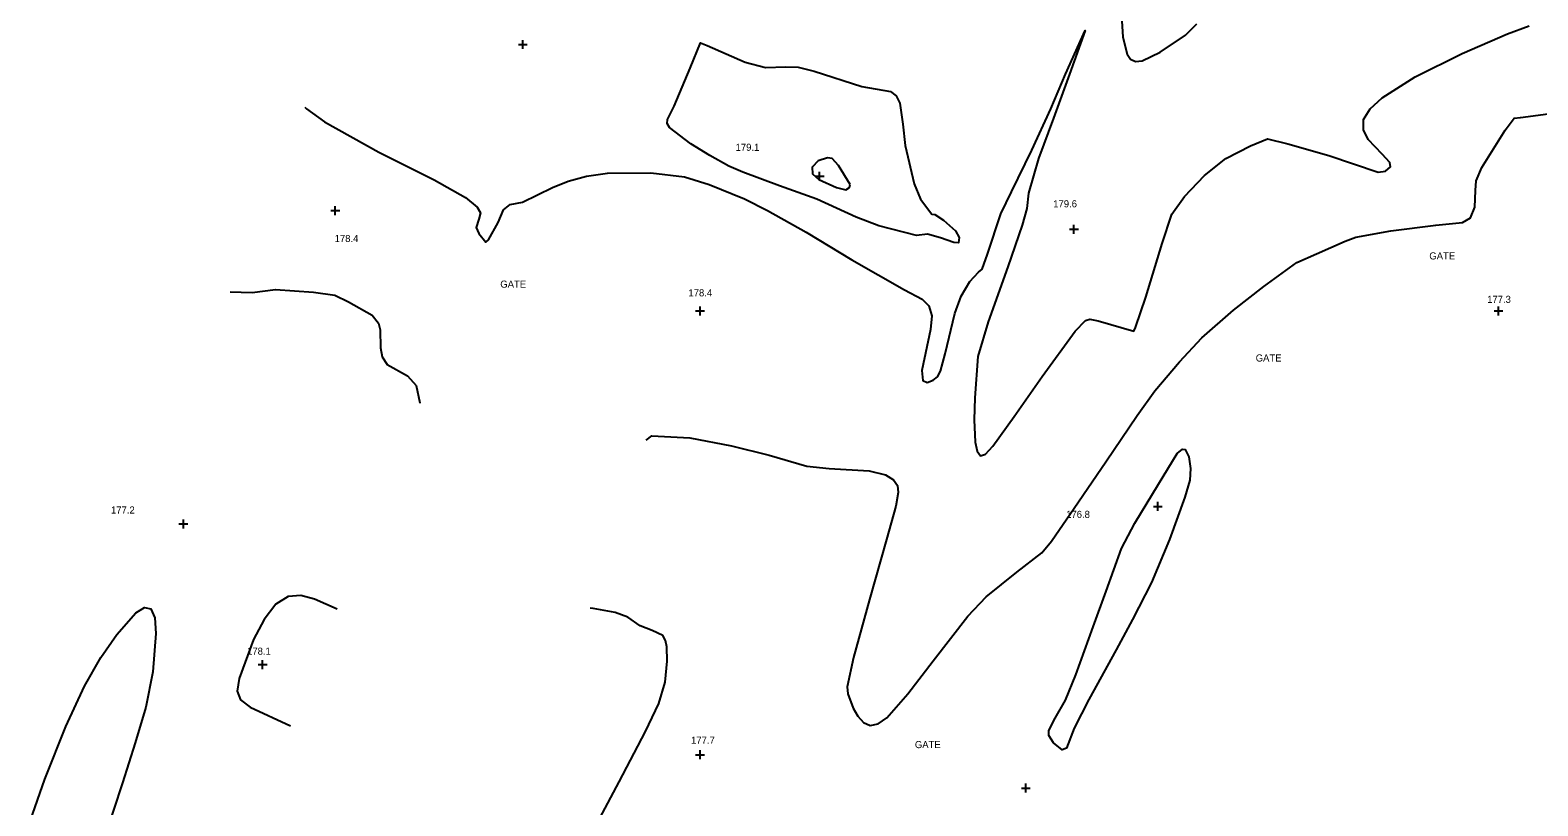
# Model space of a CAD drawing. Extents: x 1475150 to 2003689, y 770235 to 1112803.
# Drawn here: x 1997136.2 to 1997561.1, y 776485.6 to 776704.1 of the extents above; entities that cross this region are included whole.
import ezdxf

# ---------------------------------------------------------------- set-up
doc = ezdxf.new("R2010")
doc.units = 0
for name, color, linetype in [('RD_DTM_Major1', 7, 'Continuous'), ('RD_DTM_Minor1', 7, 'Continuous'), ('RD_DTM_Spot_Elev', 7, 'Continuous'), ('RD_TX_Misc1', 7, 'Continuous')]:
    doc.layers.add(name, color=color, linetype=linetype)

msp = doc.modelspace()

# ---------------------------------------------------------------- linework, layer by layer
at = {"layer": 'RD_DTM_Major1'}
msp.add_lwpolyline([(1997443.54, 776711.31), (1997444.13, 776702.06), (1997445.33, 776697.3), (1997446.33, 776695.91), (1997447.72, 776695.28), (1997449.6, 776695.44), (1997454.69, 776697.86), (1997461.79, 776702.67), (1997465.01, 776705.84)], dxfattribs=at)
at = {"layer": 'RD_DTM_Minor1'}
for points in [[(1997213.6, 776682.39), (1997214.08, 776681.94), (1997219.15, 776678.26), (1997234.51, 776669.73), (1997250.05, 776661.89), (1997258.86, 776656.95), (1997262.23, 776654.26), (1997263.12, 776652.61), (1997262.63, 776650.87), (1997261.92, 776648.45), (1997262.65, 776646.82), (1997264.63, 776644.36), (1997265.4, 776645.05), (1997268.13, 776649.88), (1997269.63, 776653.46), (1997271.47, 776654.94), (1997275, 776655.63), (1997283.44, 776659.79), (1997287.81, 776661.55), (1997292.99, 776662.96), (1997298.9, 776663.77), (1997311.13, 776663.87), (1997320.62, 776662.72), (1997327.54, 776660.62), (1997337.51, 776656.52), (1997343.96, 776653.32), (1997354.85, 776647.14), (1997367.79, 776639.37), (1997382.58, 776630.9), (1997387.56, 776628.27), (1997389.47, 776626.39), (1997390.35, 776623.62), (1997389.91, 776619.75), (1997387.46, 776608.22), (1997387.79, 776605.41), (1997388.97, 776604.81), (1997390.65, 776605.45), (1997391.89, 776606.4), (1997392.72, 776608.04), (1997394.09, 776612.89), (1997396.76, 776624.3), (1997398.55, 776629.13), (1997401.01, 776633.29), (1997403.5, 776635.89), (1997404.45, 776636.8), (1997405.98, 776640.96), (1997409.71, 776652.3), (1997412.76, 776658.55), (1997418.49, 776670.25), (1997423.8, 776681.93), (1997427.96, 776691.69), (1997433.55, 776703.99), (1997429.12, 776691.68), (1997424.61, 776679.28), (1997420.39, 776667.91), (1997417.54, 776658.15), (1997417.09, 776653.88), (1997415.81, 776649.15), (1997411.7, 776637.38), (1997406.17, 776621.88), (1997403.31, 776612.2), (1997402.44, 776600.51), (1997402.27, 776594.29), (1997402.53, 776588.03), (1997403.05, 776585.45), (1997403.99, 776584.15), (1997405.47, 776584.67), (1997407.54, 776586.87), (1997413.5, 776595.23), (1997421.44, 776606.5), (1997430.74, 776619.25), (1997433.6, 776622.33), (1997434.82, 776622.64), (1997437.15, 776622.18), (1997447.21, 776619.34), (1997447.69, 776620.3), (1997450.6, 776628.88), (1997455.2, 776643.95), (1997457.94, 776652.28), (1997461.49, 776657.25), (1997467.17, 776663.15), (1997473.19, 776667.89), (1997480.09, 776671.52), (1997484.88, 776673.44), (1997490.65, 776672.08), (1997502.21, 776668.77), (1997516.08, 776664.12), (1997518.15, 776664.36), (1997519.59, 776665.56), (1997519.38, 776666.76), (1997517.23, 776669.12), (1997513.25, 776673.32), (1997511.91, 776675.98), (1997511.93, 776678.9), (1997513.81, 776681.95), (1997517.22, 776685.05), (1997526.47, 776690.88), (1997539.73, 776697.45), (1997552.56, 776703.07), (1997558.68, 776705.31)], [(1997317.74, 776682.62), (1997322.21, 776693.35), (1997325.16, 776700.47), (1997327, 776699.72), (1997337.66, 776695.09), (1997343.39, 776693.59), (1997349.21, 776693.7), (1997352.65, 776693.62), (1997357.19, 776692.53), (1997370.58, 776688.2), (1997378.66, 776686.78), (1997380.29, 776685.57), (1997381.29, 776683.48), (1997382.1, 776677.6), (1997382.76, 776671.54), (1997385.32, 776660.76), (1997387.08, 776656.44), (1997390.28, 776652.22), (1997391.16, 776652.16), (1997393.58, 776650.59), (1997397.02, 776647.57), (1997398.05, 776645.71), (1997397.81, 776644.21), (1997396.52, 776644.29), (1997392.78, 776645.55), (1997389.1, 776646.6), (1997386, 776646.19), (1997375.36, 776648.96), (1997369, 776651.37), (1997357.91, 776656.44), (1997347.36, 776660.25), (1997337.03, 776664.08), (1997333.06, 776665.75), (1997327.74, 776668.8), (1997322.37, 776672.05), (1997316.36, 776676.65), (1997315.7, 776677.77), (1997315.82, 776678.88), (1997317.74, 776682.62)], [(1997309.85, 776588.64), (1997311.4, 776589.78), (1997322.11, 776589.25), (1997333.82, 776586.96), (1997344.46, 776584.39), (1997355.12, 776581.25), (1997361.34, 776580.65), (1997372.63, 776579.96), (1997377.23, 776578.86), (1997379.53, 776577.41), (1997380.62, 776575.87), (1997380.83, 776573.81), (1997380.13, 776570.02), (1997377.57, 776560.65), (1997372.74, 776543.75), (1997368.19, 776527.36), (1997366.48, 776519.16), (1997366.61, 776517.12), (1997368.18, 776513.14), (1997369.47, 776510.88), (1997371.07, 776509.06), (1997372.97, 776508.19), (1997375.14, 776508.67), (1997377.62, 776510.44), (1997383.57, 776517.11), (1997390.68, 776526.44), (1997400.46, 776539.07), (1997405.62, 776544.48), (1997414.27, 776551.38), (1997421.3, 776556.91), (1997424.05, 776560.16), (1997430.46, 776569.49), (1997439.32, 776582.46), (1997448.13, 776595.56), (1997453.19, 776602.45), (1997460.07, 776610.66), (1997466.42, 776617.41), (1997475.35, 776625.17), (1997483.82, 776631.89), (1997493.19, 776638.67), (1997498.73, 776641.03), (1997506.8, 776644.6), (1997509.76, 776645.76), (1997519.61, 776647.58), (1997532.29, 776649.19), (1997539.81, 776649.89), (1997542.14, 776651.25), (1997543.32, 776654.17), (1997543.54, 776658.92), (1997543.67, 776661.62), (1997545.26, 776665.41), (1997551.86, 776675.94), (1997554.4, 776679.24), (1997556.16, 776679.48), (1997565.42, 776680.66)], [(1997367.3, 776660.57), (1997364.03, 776665.92), (1997362.19, 776667.9), (1997360.93, 776668.13), (1997358.27, 776667.24), (1997356.61, 776665.51), (1997356.67, 776663.65), (1997358.44, 776661.97), (1997363.45, 776659.78), (1997366.06, 776659.08), (1997367.07, 776659.77), (1997367.3, 776660.57)], [(1997192.54, 776630.35), (1997198.79, 776630.18), (1997205.33, 776631), (1997216.03, 776630.32), (1997222.1, 776629.39), (1997225.94, 776627.56), (1997232.59, 776623.79), (1997234.41, 776621.5), (1997234.82, 776619.69), (1997234.9, 776614.62), (1997235.42, 776612.02), (1997236.87, 776609.89), (1997242.53, 776606.72), (1997245.04, 776603.96), (1997246.06, 776599.11), (1997246.04, 776598.98)], [(1997430.41, 776507.49), (1997428.23, 776501.85), (1997427.01, 776501.41), (1997424.62, 776503.31), (1997423.31, 776505.46), (1997423.3, 776506.81), (1997425.06, 776510.27), (1997428.02, 776515.39), (1997430.86, 776522.46), (1997435.81, 776536.05), (1997439.43, 776546.07), (1997443.78, 776558.13), (1997447.48, 776565.18), (1997454.14, 776576.2), (1997459.42, 776584.85), (1997460.95, 776586.04), (1997461.66, 776585.94), (1997462.73, 776583.87), (1997463.24, 776580.62), (1997463, 776577.35), (1997461.6, 776572.5), (1997457.29, 776560.62), (1997452.22, 776548.54), (1997446.85, 776538.11), (1997442.22, 776529.57), (1997434.56, 776515.6), (1997430.41, 776507.49)], [(1997136.22, 776481.27), (1997140.31, 776493.1), (1997146.28, 776507.93), (1997151.57, 776519.3), (1997156.13, 776527.36), (1997160.62, 776533.9), (1997165.98, 776539.93), (1997168.4, 776541.44), (1997170.25, 776541.1), (1997171.31, 776538.51), (1997171.66, 776534.19), (1997170.83, 776523.39), (1997168.78, 776513.37), (1997165.83, 776503.33), (1997162.25, 776492.06), (1997157.13, 776476.73)], [(1997222.77, 776541.04), (1997216.34, 776543.8), (1997212.52, 776544.81), (1997208.92, 776544.53), (1997205.47, 776542.39), (1997202.16, 776538.11), (1997199.17, 776532.48), (1997195.13, 776521.45), (1997194.59, 776517.91), (1997195.49, 776515.49), (1997198.21, 776513.44), (1997209.54, 776508.1)], [(1997286.62, 776467.18), (1997290.23, 776471.12), (1997294.31, 776477.55), (1997302.2, 776492.37), (1997309.65, 776506.51), (1997313.41, 776514.39), (1997315.15, 776520.48), (1997315.7, 776526.34), (1997315.67, 776530.4), (1997315.28, 776532.17), (1997314.46, 776533.54), (1997311.48, 776535), (1997308.11, 776536.27), (1997304.64, 776538.75), (1997301.04, 776540.1), (1997294.91, 776541.22), (1997293.99, 776541.28)]]:
    msp.add_lwpolyline(points, dxfattribs=at)
at = {"layer": 'RD_DTM_Spot_Elev'}
for p, q in [((1997273.8, 776700.04), (1997276.3, 776700.04)), ((1997275.05, 776698.79), (1997275.05, 776701.29)), ((1997358.68, 776661.68), (1997358.68, 776664.18)), ((1997357.43, 776662.93), (1997359.93, 776662.93)), ((1997220.95, 776653.24), (1997223.45, 776653.24)), ((1997222.2, 776651.99), (1997222.2, 776654.49)), ((1997429.1, 776647.99), (1997431.6, 776647.99)), ((1997430.35, 776646.74), (1997430.35, 776649.24)), ((1997325, 776623.75), (1997325, 776626.25)), ((1997550, 776623.75), (1997550, 776626.25)), ((1997323.75, 776625), (1997326.25, 776625)), ((1997548.75, 776625), (1997551.25, 776625)), ((1997453.98, 776568.69), (1997453.98, 776571.19)), ((1997452.73, 776569.94), (1997455.23, 776569.94)), ((1997178.15, 776564.99), (1997180.65, 776564.99)), ((1997179.4, 776563.74), (1997179.4, 776566.24)), ((1997200.48, 776525.37), (1997202.98, 776525.37)), ((1997201.73, 776524.12), (1997201.73, 776526.62)), ((1997323.75, 776500), (1997326.25, 776500)), ((1997325, 776498.75), (1997325, 776501.25)), ((1997415.55, 776490.63), (1997418.05, 776490.63)), ((1997416.8, 776489.38), (1997416.8, 776491.88))]:
    msp.add_line(p, q, dxfattribs=at)

# ---------------------------------------------------------------- texts
for s, p in [('179.1', (1997335.01, 776670.08)), ('179.6', (1997424.52, 776654.17)), ('178.4', (1997222.02, 776644.39)), ('178.4', (1997321.72, 776629.09)), ('177.3', (1997546.79, 776627.26)), ('177.2', (1997159, 776567.93)), ('176.8', (1997428.16, 776566.7)), ('178.1', (1997197.35, 776528.17)), ('177.7', (1997322.46, 776503.09))]:
    msp.add_text(s, height=2, dxfattribs=at).set_placement(p)
at = {"layer": 'RD_TX_Misc1'}
for p in [(1997530.5, 776639.49), (1997268.7, 776631.54), (1997481.57, 776610.74), (1997385.53, 776501.86)]:
    msp.add_text('GATE', height=2, dxfattribs=at).set_placement(p)

doc.saveas('drawing.dxf')
